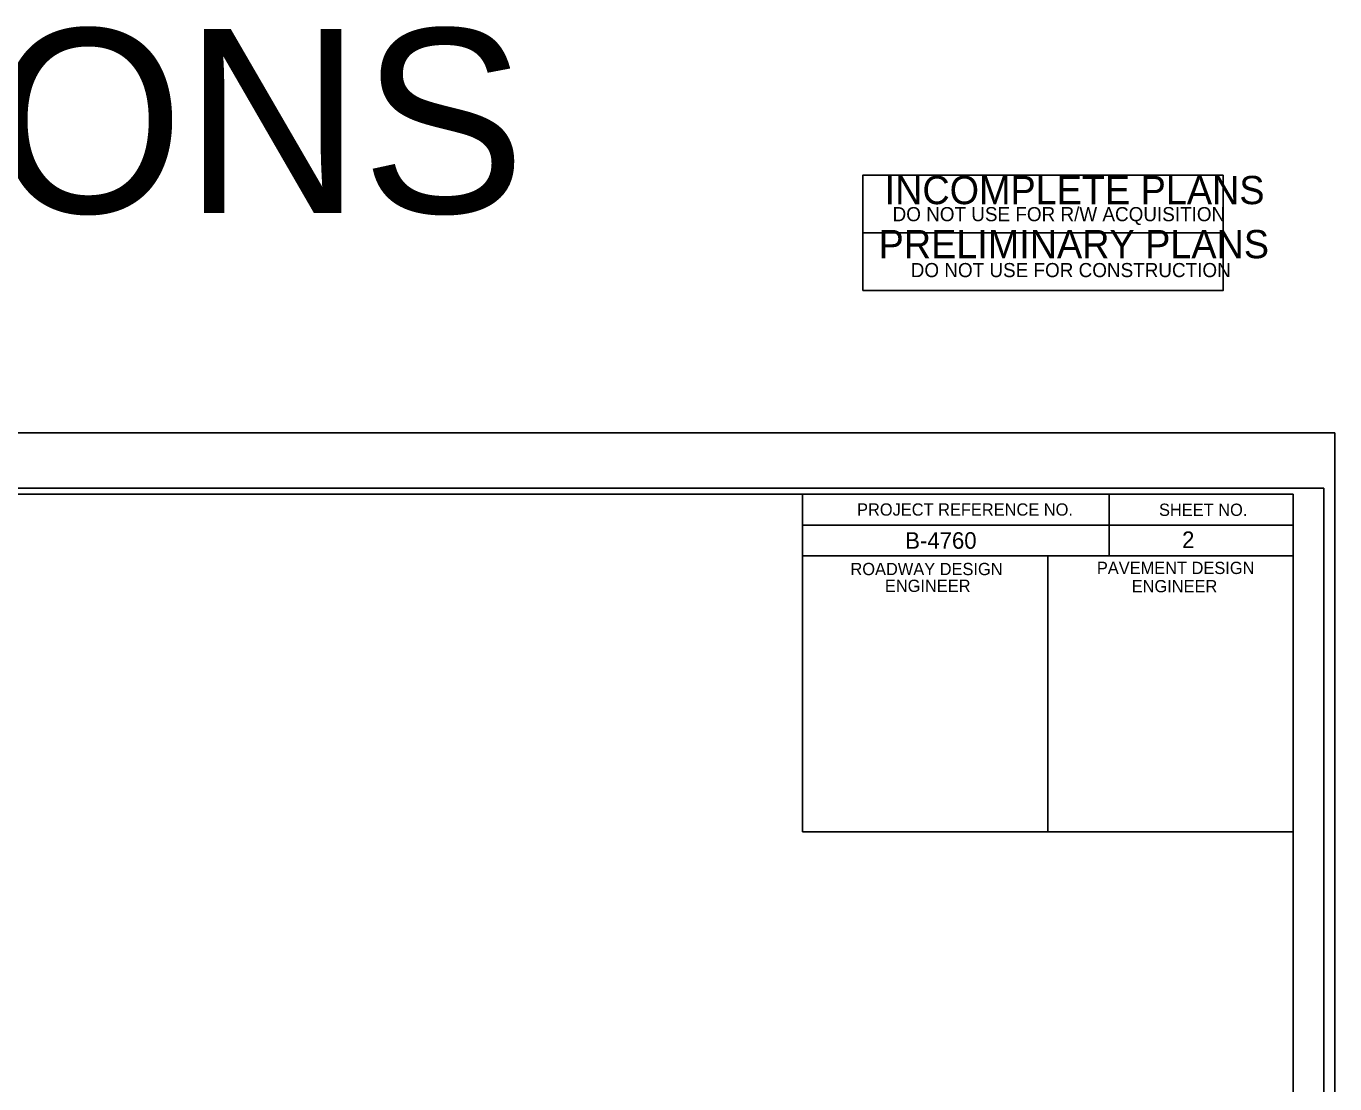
# Model space of a CAD drawing. Extents: x 981824 to 982276, y 44828 to 45204.
# Drawn here: x 982186.38 to 982229.08, y 45156.74 to 45191.24 of the extents above; entities that cross this region are included whole.
import ezdxf

# ---------------------------------------------------------------- set-up
doc = ezdxf.new("R2010")
doc.units = 0
for name, color, linetype in [('Old_Level_1', 7, 'Continuous'), ('Old_Level_18', 7, 'Continuous'), ('Old_Level_40', 7, 'Continuous'), ('Old_Level_44', 7, 'Continuous'), ('Old_Level_50', 7, 'Continuous'), ('Old_Level_51', 7, 'Continuous'), ('Old_Level_52', 7, 'Continuous'), ('Sheet Sticker Incomplete CELL', 7, 'Continuous'), ('Sheet Sticker Preliminary CELL', 7, 'Continuous')]:
    doc.layers.add(name, color=color, linetype=linetype)

msp = doc.modelspace()

# ---------------------------------------------------------------- linework, layer by layer
at = {"layer": 'Old_Level_1'}
msp.add_line((982228.72, 45176.173), (982228.72, 45176.173), dxfattribs=at)
at = {"layer": 'Old_Level_18'}
msp.add_lwpolyline([(982227.72, 45175.969), (982107.72, 45175.969), (982107.72, 45091.969), (982227.72, 45091.969)], close=True, dxfattribs=at)
at = {"layer": 'Old_Level_40'}
for p, q in [((982221.72, 45175.965), (982221.72, 45173.965)), ((982211.716, 45174.965), (982227.72, 45174.965)), ((982219.72, 45173.965), (982219.72, 45164.969))]:
    msp.add_line(p, q, dxfattribs=at)
for points in [[(982211.716, 45175.969), (982227.72, 45175.969), (982227.72, 45173.965), (982211.716, 45173.965)], [(982211.716, 45173.965), (982219.72, 45173.965), (982219.72, 45164.965), (982211.716, 45164.965)], [(982219.72, 45173.965), (982227.72, 45173.965), (982227.72, 45164.965), (982219.72, 45164.965)]]:
    msp.add_lwpolyline(points, close=True, dxfattribs=at)
at = {"layer": 'Old_Level_50'}
msp.add_line((982229.08, 45177.969), (982229.08, 45177.969), dxfattribs=at)
msp.add_lwpolyline([(982228.72, 45176.173), (982095.4, 45176.173), (982095.4, 45091.765), (982228.72, 45091.765)], close=True, dxfattribs=at)
at = {"layer": 'Old_Level_51'}
msp.add_lwpolyline([(982229.08, 45177.969), (982094.36, 45177.969), (982094.36, 45089.969), (982229.08, 45089.969)], close=True, dxfattribs=at)
at = {"layer": 'Old_Level_52'}
msp.add_line((982228.72, 45176.173), (982228.72, 45176.173), dxfattribs=at)
at = {"layer": 'Sheet Sticker Incomplete CELL'}
msp.add_lwpolyline([(982213.675, 45184.496), (982213.675, 45186.376), (982225.435, 45186.376), (982225.435, 45184.496)], close=True, dxfattribs=at)
at = {"layer": 'Sheet Sticker Preliminary CELL'}
msp.add_lwpolyline([(982213.675, 45182.616), (982213.675, 45184.496), (982225.435, 45184.496), (982225.435, 45182.616)], close=True, dxfattribs=at)

# ---------------------------------------------------------------- texts
at = {"layer": 'Old_Level_1'}
msp.add_text('TYPICAL SECTIONS', height=6, dxfattribs=at).set_placement((982125.989, 45185.148))
at = {"layer": 'Old_Level_44'}
for s, height, p in [('PROJECT REFERENCE NO.', 0.40001, (982213.492, 45175.273)), ('SHEET NO.', 0.4, (982223.344, 45175.265)), (' B-4760', 0.54, (982214.862, 45174.193)), (' 2 ', 0.54, (982223.896, 45174.217)), ('PAVEMENT DESIGN', 0.40001, (982221.316, 45173.369)), ('ROADWAY DESIGN', 0.40001, (982213.276, 45173.333)), ('ENGINEER', 0.4, (982214.4, 45172.785)), ('ENGINEER', 0.4, (982222.452, 45172.773))]:
    msp.add_text(s, height=height, dxfattribs=at).set_placement(p)
at = {"layer": 'Sheet Sticker Incomplete CELL'}
for s, height, p in [('INCOMPLETE PLANS', 0.9216, (982214.391, 45185.432)), ('DO NOT USE FOR R/W ACQUISITION', 0.4608, (982214.651, 45184.876))]:
    msp.add_text(s, height=height, dxfattribs=at).set_placement(p)
at = {"layer": 'Sheet Sticker Preliminary CELL'}
for s, height, p in [('PRELIMINARY PLANS', 0.9216, (982214.195, 45183.668)), ('DO NOT USE FOR CONSTRUCTION', 0.4608, (982215.243, 45183.052))]:
    msp.add_text(s, height=height, dxfattribs=at).set_placement(p)

doc.saveas('drawing.dxf')
